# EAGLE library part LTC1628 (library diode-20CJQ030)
Linear Tech's LTC1628 High Efficiency, 2-Phase Synchronous Step-Down Switching Regulators Description: The LTC®1628/LTC1628-PG are high performance dual step-down switching regulator controllers that drive all N-channel synchronous power MOSFET stages. A constant frequency current mode architecture allows adjustment of the frequency up to 300kHz. Power loss and noise due to the ESR of the input capacitors are minimized by operating the two controller output stages out of phase. OPTI-LOOP compensation allows the transient response to be optimized over a wide range of output capacitance and ESR values. The precision 0.8V reference and power good output indicator are compatible with future microprocessor generations, and a wide 3.5V to 30V (36V maximum) input supply range encompasses all battery chemistries. A RUN/SS pin for each controller provides both soft-start and optional timed, short-circuit shutdown. Current foldback limits MOSFET dissipation during short-circuit conditions when overcurrent latchoff is disabled. Output overvoltage protection circuitry latches on the bottom MOSFET until VOUT returns to normal. The FCB mode pin can select among Burst Mode, constant frequency mode and continuous inductor current mode or regulate a secondary winding. The LTC1628-PG includes a power good output pin that replaces the FLTCPL, fault coupling control pin of the LTC1628. Features: Out-of-Phase Controllers Reduce Required Input Capacitance and Power Supply Induced Noise OPTI-LOOP®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
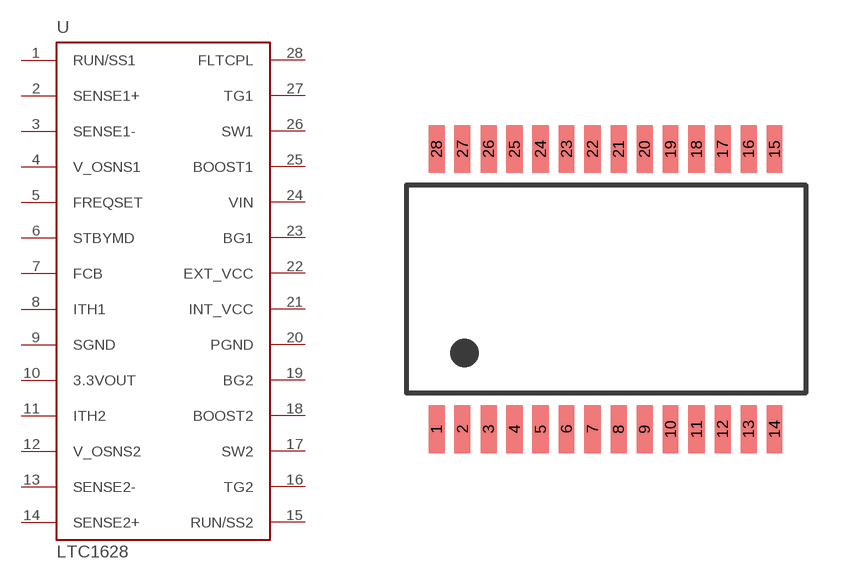
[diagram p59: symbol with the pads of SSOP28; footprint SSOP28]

Designator prefix U

## LTC1628  [SSOP28]
1  RUN/SS1  in
2  SENSE1+  in
3  SENSE1-  in
4  V_OSNS1  in
5  FREQSET  in
6  STBYMD  in
7  FCB  in
8  ITH1  out
9  SGND  pwr
10  3.3VOUT  out
11  ITH2  out
12  V_OSNS2  in
13  SENSE2-  in
14  SENSE2+  in
15  RUN/SS2  in
16  TG2  out
17  SW2  out
18  BOOST2  in
19  BG2  out
20  PGND  pwr
21  INT_VCC  out
22  EXT_VCC  in
23  BG1  out
24  VIN  pwr
25  BOOST1  in
26  SW1  out
27  TG1  out
28  FLTCPL  in

## Footprint SSOP28 (pad centres in mm)
SSOP-28 Package E.g. LTC1628
smd 0.4 x 1.2: 1 -4.225,-3.5; 2 -3.575,-3.5; 3 -2.925,-3.5; 4 -2.275,-3.5; 5 -1.625,-3.5; 6 -0.975,-3.5; 7 -0.325,-3.5; 8 0.325,-3.5; 9 0.975,-3.5; 10 1.625,-3.5; 11 2.275,-3.5; 12 2.925,-3.5; 13 3.575,-3.5; 14 4.225,-3.5; 15 4.225,3.5; 16 3.575,3.5; 17 2.925,3.5; 18 2.275,3.5; 19 1.625,3.5; 20 0.975,3.5; 21 0.325,3.5; 22 -0.325,3.5; 23 -0.975,3.5; 24 -1.625,3.5; 25 -2.275,3.5; 26 -2.925,3.5; 27 -3.575,3.5; 28 -4.225,3.5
